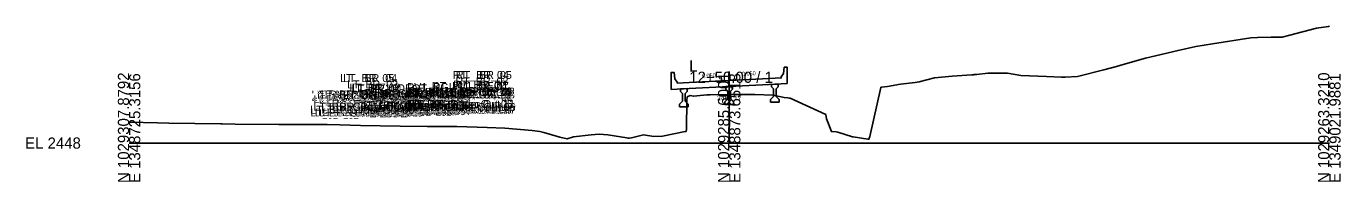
# Model space of a CAD drawing. Extents: x -26 to 1453, y -10 to 4527.
# Drawn here: x -25.7 to 302.8, y 2490.3 to 2529.3 of the extents above; entities that cross this region are included whole.
import ezdxf

# ---------------------------------------------------------------- set-up
doc = ezdxf.new("R2010")
doc.units = 0
for name, color, linetype in [('Default', 7, 'Continuous'), ('Exist Cross Section Cell', 7, 'Continuous'), ('Exist XS Center Line Elevation Label', 7, 'Continuous'), ('Exist XS Ground Line', 7, 'Continuous'), ('Prop CMT Concrete Structures', 7, 'Continuous'), ('Prop XS SE Text', 7, 'Continuous')]:
    doc.layers.add(name, color=color, linetype=linetype)

msp = doc.modelspace()

# ---------------------------------------------------------------- linework, layer by layer
at = {"layer": 'Exist Cross Section Cell'}
for p, q in [((150, 2500), (150, 2517.89)), ((0, 2500), (150, 2500)), ((150, 2500), (300, 2500))]:
    msp.add_line(p, q, dxfattribs=at)
at = {"layer": 'Exist XS Ground Line'}
msp.add_lwpolyline([(0, 2505.21), (7.08, 2505.05), (9.93, 2505), (22.91, 2504.8), (23.3, 2504.8), (26.55, 2504.75), (37.42, 2504.64), (49.5, 2504.63), (52.69, 2504.56), (57.85, 2504.39), (67.79, 2504.26), (74.49, 2504.14), (81.88, 2504.17), (89.5, 2503.88), (93.93, 2503.71), (100.74, 2503.19), (102.64, 2502.93), (103.65, 2502.65), (105.65, 2502.06), (107.65, 2501.49), (109.46, 2501.06), (111.12, 2501.59), (115.47, 2502.08), (117.52, 2502.23), (119.63, 2502.1), (124.38, 2501.31), (124.73, 2501.2), (124.81, 2501.19), (124.97, 2501.23), (125.6, 2501.35), (128.55, 2502.06), (131.2, 2501.68), (133.31, 2501.7), (138.97, 2502.87), (139.21, 2502.91), (139.28, 2502.93), (139.29, 2503.47), (139.42, 2510.79), (139.46, 2511.56), (140.23, 2511.95), (141.07, 2511.74), (144.38, 2512.07), (144.65, 2512.11), (144.65, 2512.11), (144.85, 2512.12), (145.25, 2512.12), (150, 2512.17), (153.49, 2512.2), (156.37, 2512.13), (160.96, 2512.03), (163.76, 2511.44), (164.63, 2511.36), (165.02, 2511.21), (165.21, 2511.29), (174.12, 2507.15), (174.35, 2506.05), (175.56, 2502.89), (176.7, 2502.8), (177.12, 2502.7), (180.83, 2501.59), (180.95, 2501.53), (184.62, 2501), (184.93, 2500.96), (185.12, 2501.61), (187.86, 2513.93), (188.04, 2513.99), (189.53, 2514.16), (192.79, 2514.73), (196.49, 2515.19), (197.49, 2515.34), (201.3, 2516.38), (205.74, 2516.77), (210.67, 2517.11), (211.06, 2517.13), (211.24, 2517.14), (211.87, 2517.18), (214.63, 2517.54), (217.93, 2517.52), (219.53, 2517.5), (222.91, 2516.93), (225.04, 2516.88), (227.13, 2516.75), (229.34, 2516.64), (233.04, 2516.54), (233.97, 2516.48), (237.03, 2516.71), (243.61, 2518.31), (246.76, 2519.15), (248.46, 2519.68), (254.08, 2521.23), (262.21, 2523.23), (266.61, 2524.19), (270.76, 2524.85), (280.37, 2526.34), (282.02, 2526.44), (285.48, 2526.55), (286.47, 2526.49), (288.22, 2526.51), (290.14, 2527.04), (296.77, 2528.81), (299.8, 2529.22), (300, 2529.27)], dxfattribs=at)
at = {"layer": 'Prop CMT Concrete Structures'}
for points in [[(150, 2515.68), (140, 2515.18), (137, 2515.03), (136.99, 2515.28), (136.41, 2516.11), (136.24, 2517.7), (135.5, 2517.7), (135.5, 2513.46)], [(150, 2515.68), (160, 2516.18), (163, 2516.33), (163.01, 2516.58), (163.59, 2517.41), (163.76, 2519), (164.5, 2519), (164.5, 2514.91)], [(135.5, 2513.46), (140, 2513.68), (150, 2514.18)], [(139.46, 2513.65), (138.62, 2513.61), (137.79, 2513.57)], [(137.79, 2513.57), (137.79, 2512.94)], [(139.46, 2512.94), (139.46, 2513.65)], [(150, 2514.18), (149.17, 2514.14)], [(149.17, 2514.14), (149.17, 2513.51)], [(149.17, 2513.51), (149.67, 2513.01)], [(150, 2514.18), (150, 2515.68)], [(150, 2514.18), (150, 2515.68)], [(164.5, 2514.91), (160, 2514.68), (150, 2514.18)], [(150, 2514.18), (150.83, 2514.22)], [(150, 2509.68), (150, 2514.18)], [(150, 2509.68), (150, 2514.18)], [(150.83, 2513.51), (150.33, 2513.01)], [(150.83, 2514.22), (150.83, 2513.51)], [(160.54, 2514.71), (161.38, 2514.75), (162.21, 2514.79)], [(160.54, 2514.08), (160.54, 2514.71)], [(161.04, 2513.58), (160.54, 2514.08)], [(161.04, 2511.67), (161.04, 2513.58)], [(162.21, 2514.08), (161.71, 2513.58)], [(161.71, 2513.58), (161.71, 2511.67)], [(162.21, 2514.79), (162.21, 2514.08)], [(138.29, 2510.53), (137.54, 2509.78)], [(137.79, 2512.94), (138.29, 2512.44)], [(138.29, 2512.44), (138.29, 2510.53)], [(138.96, 2512.44), (139.46, 2512.94)], [(138.96, 2510.53), (138.96, 2512.44)], [(139.71, 2509.78), (138.96, 2510.53)], [(149.67, 2511.1), (148.92, 2510.35)], [(148.92, 2510.35), (148.92, 2509.68)], [(149.67, 2513.01), (149.67, 2511.1)], [(150.33, 2513.01), (150.33, 2511.1)], [(150.33, 2511.1), (151.08, 2510.35)], [(151.08, 2510.35), (151.08, 2509.68)], [(160.29, 2510.92), (161.04, 2511.67)], [(160.29, 2510.25), (160.29, 2510.92)], [(162.46, 2510.25), (161.38, 2510.25), (160.29, 2510.25)], [(161.71, 2511.67), (162.46, 2510.92)], [(162.46, 2510.92), (162.46, 2510.25)], [(137.54, 2509.78), (137.54, 2509.11)], [(137.54, 2509.11), (138.62, 2509.11), (139.71, 2509.11)], [(139.71, 2509.11), (139.71, 2509.78)], [(148.92, 2509.68), (150, 2509.68)], [(151.08, 2509.68), (150, 2509.68)]]:
    msp.add_lwpolyline(points, dxfattribs=at)

# ---------------------------------------------------------------- texts
at = {"layer": 'Default'}
for s, height, p in [('LT_ BR_05', 2, (52.74, 2515.28)), ('LT_ BR_04', 2, (53.48, 2515.28)), ('RT_ BR_04', 2, (80.95, 2516.06)), ('RT_ BR_05', 2, (81.69, 2516.06)), ('LT_BR_Girder Out 14', 2, (47.89, 2511.19)), ('LT_BR_03', 2, (54.46, 2513.7)), ('LT_BR_02', 2, (55.05, 2512.87)), ('LT_BR_01', 2, (55.62, 2512.62)), ('LT_PV1_OEOT', 2, (55.74, 2512.71)), ('LT_BR_Girder Mid 02', 2, (57.35, 2511.48)), ('RT_BR_Girder Mid 02', 2, (58.97, 2511.53)), ('RT_BR_Girder Out 14', 2, (68.93, 2511.82)), ('RT_BR_Girder Out 13', 2, (68.93, 2511.18)), ('PV1_PGL', 2, (69.47, 2513.01)), ('RT_BR_Girder Out 01', 2, (69.68, 2511.85)), ('BR_PGL', 2, (69.83, 2511.51)), ('RT_BR_Girder Out 02', 2, (69.95, 2511.87)), ('RT_BR_Girder Out 03', 2, (69.95, 2511.18)), ('RT_PV1_OEOT', 2, (75.69, 2513.31)), ('RT_BR_07', 2, (78.01, 2511.81)), ('RT_BR_02', 2, (81.02, 2513.65)), ('RT_BR_01', 2, (81.57, 2513.4)), ('RT_BR_03', 2, (81.6, 2514.48)), ('RT_BR_06', 2, (82.46, 2511.94)), ('LT_BR_Girder Out 02', 2, (45.58, 2511.14)), ('LT_BR_Girder Out 03', 2, (45.58, 2510.5)), ('LT_BR_Girder Out 04', 2, (46.08, 2510)), ('LT_BR_Girder Out 05', 2, (46.08, 2508.08)), ('LT_BR_Girder Out 01', 2, (46.98, 2511.16)), ('LT_BR_Girder Out 12', 2, (47.39, 2510)), ('LT_BR_Girder Out 13', 2, (47.89, 2510.5)), ('LT_BR_Girder Out 11', 2, (47.96, 2508.08)), ('LT_BR_06', 2, (53.51, 2511.07)), ('LT_BR_Girder Mid 03', 2, (57.35, 2510.84)), ('LT_BR_Girder Mid 04', 2, (57.85, 2510.34)), ('LT_BR_Girder Mid 05', 2, (57.85, 2508.42)), ('LT_BR_07', 2, (58.06, 2511.21)), ('RT_BR_Girder Mid 04', 2, (58.47, 2510.34)), ('RT_BR_Girder Mid 05', 2, (58.47, 2508.42)), ('RT_BR_Girder Mid 03', 2, (58.97, 2510.84)), ('RT_BR_Girder Out 10', 2, (68.6, 2508.01)), ('RT_BR_Girder Out 12', 2, (69.43, 2510.68)), ('RT_BR_Girder Out 04', 2, (69.45, 2510.68)), ('RT_BR_Girder Out 05', 2, (69.45, 2508.76)), ('RT_BR_Girder Out 11', 2, (70, 2508.76)), ('RT_BR_Girder Out 06', 2, (70.15, 2508.01)), ('LT_BR_Girder Out 06', 2, (45.28, 2507.33)), ('LT_BR_Girder Out 07', 2, (45.33, 2506.66)), ('LT_BR_Girder Out 08', 2, (46.41, 2506.66)), ('LT_BR_Girder Out 09', 2, (47.49, 2506.66)), ('LT_BR_Girder Out 10', 2, (48.06, 2507.33)), ('LT_BR_Girder Mid 06', 2, (57.05, 2507.67)), ('LT_BR_Girder Mid 07', 2, (57.1, 2507.01)), ('RT_BR_Girder Mid 06', 2, (59.17, 2507.67)), ('RT_BR_Girder Mid 07', 2, (59.22, 2507.01)), ('BR_Girder Mid 08', 2, (60.87, 2507.01)), ('RT_BR_Girder Out 09', 2, (68.03, 2507.35)), ('RT_BR_Girder Out 08', 2, (69.12, 2507.35)), ('RT_BR_Girder Out 07', 2, (70.2, 2507.35)), ('-', 0.0001, (0, 2500)), ('-', 0.0001, (0, 2500)), ('-', 0.0001, (0, 2500)), ('-', 0.0001, (0, 2500))]:
    msp.add_text(s, height=height, dxfattribs=at).set_placement(p)
at = {"layer": 'Exist Cross Section Cell'}
for s, p in [('L', (140, 2517.89)), ('12+50.00 / 1', (140, 2515.09)), ('EL 2448', (-26, 2498.6))]:
    msp.add_text(s, height=2.8, dxfattribs=at).set_placement(p)
for s, p in [('N 1029307.8792', (0, 2490)), ('E 1348725.3156', (2.8, 2490)), ('N 1029285.6001', (150, 2490)), ('E 1348873.6518', (152.8, 2490)), ('N 1029263.3210', (300, 2490)), ('E 1349021.9881', (302.8, 2490))]:
    msp.add_text(s, height=2.8, rotation=90, dxfattribs=at).set_placement(p)
at = {"layer": 'Exist XS Center Line Elevation Label'}
msp.add_text('2460.17', height=1.23, dxfattribs=at).set_placement((146.94, 2510.67))
at = {"layer": 'Prop XS SE Text'}
for p in [(143.2, 2516.34), (153.2, 2516.84)]:
    msp.add_text('0.050', height=1, rotation=2.8624, dxfattribs=at).set_placement(p)

doc.saveas('drawing.dxf')
